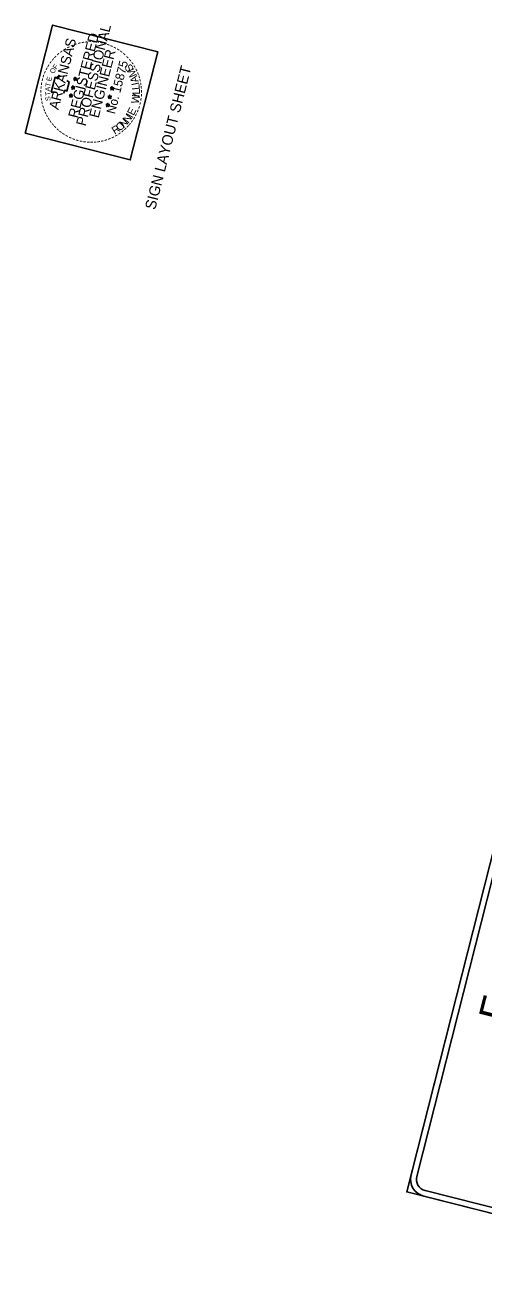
# Model space of a CAD drawing. Extents: x 670257 to 671518, y 737783 to 738188.
# Drawn here: x 670664 to 670687, y 738025.9 to 738088.5 of the extents above; entities that cross this region are included whole.
import ezdxf

# ---------------------------------------------------------------- set-up
doc = ezdxf.new("R2010")
doc.units = 0
for name, color, linetype in [('R_Border Notes', 7, 'Continuous'), ('R_Border PE', 7, 'Continuous'), ('R_Border Prem', 7, 'Continuous'), ('R_SIGN', 7, 'Continuous')]:
    doc.layers.add(name, color=color, linetype=linetype)

msp = doc.modelspace()

# ---------------------------------------------------------------- linework, layer by layer
at = {"layer": 'R_Border PE'}
for p, q in [((670666.448, 738085.809), (670666.513, 738085.811)), ((670666.535, 738085.787), (670666.448, 738085.809)), ((670666.448, 738085.809), (670666.511, 738085.806)), ((670666.448, 738085.809), (670666.507, 738085.799)), ((670666.448, 738085.809), (670666.507, 738085.789)), ((670666.448, 738085.809), (670666.506, 738085.784)), ((670666.448, 738085.809), (670666.502, 738085.78)), ((670666.487, 738085.709), (670666.535, 738085.787)), ((670666.487, 738085.709), (670666.51, 738085.77)), ((670666.487, 738085.709), (670666.514, 738085.767)), ((670666.487, 738085.709), (670666.517, 738085.766)), ((670666.487, 738085.709), (670666.526, 738085.761)), ((670666.487, 738085.709), (670666.531, 738085.76)), ((670666.487, 738085.709), (670666.536, 738085.759)), ((670666.53, 738085.879), (670666.516, 738085.802)), ((670666.53, 738085.879), (670666.524, 738085.805)), ((670666.53, 738085.879), (670666.529, 738085.804)), ((670666.53, 738085.879), (670666.535, 738085.787)), ((670666.53, 738085.879), (670666.538, 738085.82)), ((670666.53, 738085.879), (670666.541, 738085.822)), ((670666.53, 738085.879), (670666.545, 738085.826)), ((670666.594, 738085.716), (670666.534, 738085.762)), ((670666.621, 738085.82), (670666.535, 738085.787)), ((670666.594, 738085.716), (670666.535, 738085.787)), ((670666.621, 738085.82), (670666.542, 738085.806)), ((670666.594, 738085.716), (670666.542, 738085.762)), ((670666.621, 738085.82), (670666.544, 738085.811)), ((670666.594, 738085.716), (670666.545, 738085.767)), ((670666.621, 738085.82), (670666.551, 738085.801)), ((670666.621, 738085.82), (670666.554, 738085.782)), ((670666.594, 738085.716), (670666.554, 738085.782)), ((670666.594, 738085.716), (670666.554, 738085.772)), ((670666.621, 738085.82), (670666.559, 738085.791)), ((670666.621, 738085.82), (670666.562, 738085.78)), ((670666.594, 738085.716), (670666.562, 738085.783)), ((670666.334, 738085.382), (670666.401, 738085.383)), ((670666.424, 738085.359), (670666.334, 738085.382)), ((670666.334, 738085.382), (670666.398, 738085.378)), ((670666.334, 738085.382), (670666.396, 738085.371)), ((670666.334, 738085.382), (670666.393, 738085.361)), ((670666.334, 738085.382), (670666.395, 738085.356)), ((670666.334, 738085.382), (670666.392, 738085.354)), ((670666.376, 738085.281), (670666.424, 738085.359)), ((670666.376, 738085.281), (670666.396, 738085.343)), ((670666.376, 738085.281), (670666.401, 738085.341)), ((670666.376, 738085.281), (670666.406, 738085.338)), ((670666.376, 738085.281), (670666.415, 738085.333)), ((670666.376, 738085.281), (670666.419, 738085.332)), ((670666.376, 738085.281), (670666.424, 738085.33)), ((670666.419, 738085.451), (670666.404, 738085.374)), ((670666.419, 738085.451), (670666.413, 738085.377)), ((670666.419, 738085.451), (670666.418, 738085.376)), ((670666.419, 738085.451), (670666.424, 738085.359)), ((670666.419, 738085.451), (670666.427, 738085.392)), ((670666.419, 738085.451), (670666.431, 738085.396)), ((670666.419, 738085.451), (670666.434, 738085.398)), ((670666.484, 738085.29), (670666.423, 738085.333)), ((670666.51, 738085.394), (670666.424, 738085.359)), ((670666.484, 738085.29), (670666.424, 738085.359)), ((670666.51, 738085.394), (670666.43, 738085.383)), ((670666.484, 738085.29), (670666.43, 738085.334)), ((670666.51, 738085.394), (670666.431, 738085.378)), ((670666.484, 738085.29), (670666.434, 738085.338)), ((670666.51, 738085.394), (670666.44, 738085.373)), ((670666.51, 738085.394), (670666.443, 738085.354)), ((670666.484, 738085.29), (670666.443, 738085.354)), ((670666.484, 738085.29), (670666.443, 738085.344)), ((670666.51, 738085.394), (670666.448, 738085.363)), ((670666.51, 738085.394), (670666.45, 738085.352)), ((670666.484, 738085.29), (670666.451, 738085.355)), ((670668.369, 738085.322), (670668.282, 738085.344)), ((670668.282, 738085.344), (670668.346, 738085.343)), ((670668.282, 738085.344), (670668.346, 738085.341)), ((670668.282, 738085.344), (670668.344, 738085.334)), ((670668.282, 738085.344), (670668.342, 738085.324)), ((670668.282, 738085.344), (670668.34, 738085.319)), ((670668.282, 738085.344), (670668.339, 738085.314)), ((670668.321, 738085.244), (670668.369, 738085.322)), ((670668.321, 738085.244), (670668.344, 738085.303)), ((670668.321, 738085.244), (670668.349, 738085.301)), ((670668.321, 738085.244), (670668.353, 738085.298)), ((670668.321, 738085.244), (670668.36, 738085.296)), ((670668.321, 738085.244), (670668.367, 738085.292)), ((670668.321, 738085.244), (670668.372, 738085.29)), ((670668.364, 738085.411), (670668.35, 738085.337)), ((670668.364, 738085.411), (670668.359, 738085.34)), ((670668.364, 738085.411), (670668.363, 738085.339)), ((670668.364, 738085.411), (670668.369, 738085.322)), ((670668.364, 738085.411), (670668.372, 738085.352)), ((670668.364, 738085.411), (670668.378, 738085.356)), ((670668.364, 738085.411), (670668.381, 738085.358)), ((670668.429, 738085.25), (670668.368, 738085.294)), ((670668.455, 738085.354), (670668.369, 738085.322)), ((670668.429, 738085.25), (670668.369, 738085.322)), ((670668.455, 738085.354), (670668.376, 738085.338)), ((670668.455, 738085.354), (670668.377, 738085.343)), ((670668.429, 738085.25), (670668.378, 738085.294)), ((670668.429, 738085.25), (670668.382, 738085.301)), ((670668.455, 738085.354), (670668.388, 738085.333)), ((670668.429, 738085.25), (670668.389, 738085.307)), ((670668.455, 738085.354), (670668.391, 738085.314)), ((670668.429, 738085.25), (670668.391, 738085.314)), ((670668.455, 738085.354), (670668.393, 738085.324)), ((670668.429, 738085.25), (670668.396, 738085.315)), ((670668.455, 738085.354), (670668.398, 738085.312)), ((670666.232, 738084.977), (670666.299, 738084.978)), ((670666.321, 738084.954), (670666.232, 738084.977)), ((670666.232, 738084.977), (670666.295, 738084.974)), ((670666.232, 738084.977), (670666.294, 738084.969)), ((670666.232, 738084.977), (670666.291, 738084.959)), ((670666.232, 738084.977), (670666.292, 738084.951)), ((670666.232, 738084.977), (670666.289, 738084.95)), ((670666.273, 738084.876), (670666.321, 738084.954)), ((670666.273, 738084.876), (670666.294, 738084.938)), ((670666.273, 738084.876), (670666.299, 738084.937)), ((670666.273, 738084.876), (670666.303, 738084.933)), ((670666.273, 738084.876), (670666.313, 738084.931)), ((670666.273, 738084.876), (670666.317, 738084.927)), ((670666.273, 738084.876), (670666.322, 738084.926)), ((670666.316, 738085.046), (670666.302, 738084.969)), ((670666.316, 738085.046), (670666.31, 738084.972)), ((670666.316, 738085.046), (670666.315, 738084.971)), ((670666.316, 738085.046), (670666.321, 738084.954)), ((670666.316, 738085.046), (670666.324, 738084.987)), ((670666.316, 738085.046), (670666.328, 738084.991)), ((670666.316, 738085.046), (670666.331, 738084.993)), ((670666.381, 738084.885), (670666.32, 738084.929)), ((670666.407, 738084.989), (670666.321, 738084.954)), ((670666.381, 738084.885), (670666.321, 738084.954)), ((670666.407, 738084.989), (670666.327, 738084.978)), ((670666.381, 738084.885), (670666.328, 738084.929)), ((670666.407, 738084.989), (670666.329, 738084.973)), ((670666.381, 738084.885), (670666.331, 738084.934)), ((670666.407, 738084.989), (670666.338, 738084.968)), ((670666.407, 738084.989), (670666.341, 738084.949)), ((670666.381, 738084.885), (670666.341, 738084.949)), ((670666.381, 738084.885), (670666.341, 738084.939)), ((670666.407, 738084.989), (670666.345, 738084.958)), ((670666.407, 738084.989), (670666.348, 738084.947)), ((670666.381, 738084.885), (670666.348, 738084.95)), ((670668.068, 738084.511), (670668.133, 738084.513)), ((670668.156, 738084.489), (670668.068, 738084.511)), ((670668.068, 738084.511), (670668.132, 738084.508)), ((670668.068, 738084.511), (670668.13, 738084.501)), ((670668.068, 738084.511), (670668.128, 738084.491)), ((670668.068, 738084.511), (670668.126, 738084.486)), ((670668.068, 738084.511), (670668.123, 738084.482)), ((670668.107, 738084.411), (670668.156, 738084.489)), ((670668.107, 738084.411), (670668.131, 738084.472)), ((670668.107, 738084.411), (670668.135, 738084.468)), ((670668.107, 738084.411), (670668.137, 738084.468)), ((670668.107, 738084.411), (670668.146, 738084.463)), ((670668.107, 738084.411), (670668.151, 738084.462)), ((670668.107, 738084.411), (670668.156, 738084.461)), ((670668.15, 738084.581), (670668.136, 738084.504)), ((670668.15, 738084.581), (670668.145, 738084.507)), ((670668.15, 738084.581), (670668.156, 738084.489)), ((670668.15, 738084.581), (670668.15, 738084.506)), ((670668.15, 738084.581), (670668.158, 738084.519)), ((670668.15, 738084.581), (670668.162, 738084.524)), ((670668.15, 738084.581), (670668.168, 738084.527)), ((670668.215, 738084.417), (670668.154, 738084.464)), ((670668.241, 738084.521), (670668.156, 738084.489)), ((670668.215, 738084.417), (670668.156, 738084.489)), ((670668.241, 738084.521), (670668.162, 738084.505)), ((670668.241, 738084.521), (670668.164, 738084.513)), ((670668.215, 738084.417), (670668.165, 738084.464)), ((670668.215, 738084.417), (670668.168, 738084.468)), ((670668.258, 738084.894), (670668.171, 738084.916)), ((670668.171, 738084.916), (670668.235, 738084.915)), ((670668.171, 738084.916), (670668.235, 738084.913)), ((670668.171, 738084.916), (670668.233, 738084.905)), ((670668.171, 738084.916), (670668.23, 738084.896)), ((670668.171, 738084.916), (670668.229, 738084.891)), ((670668.171, 738084.916), (670668.225, 738084.887)), ((670668.241, 738084.521), (670668.172, 738084.503)), ((670668.215, 738084.417), (670668.175, 738084.484)), ((670668.215, 738084.417), (670668.175, 738084.474)), ((670668.241, 738084.521), (670668.177, 738084.483)), ((670668.241, 738084.521), (670668.179, 738084.491)), ((670668.241, 738084.521), (670668.182, 738084.48)), ((670668.215, 738084.417), (670668.182, 738084.482)), ((670668.21, 738084.816), (670668.258, 738084.894)), ((670668.21, 738084.816), (670668.233, 738084.874)), ((670668.21, 738084.816), (670668.238, 738084.873)), ((670668.21, 738084.816), (670668.24, 738084.873)), ((670668.21, 738084.816), (670668.249, 738084.868)), ((670668.21, 738084.816), (670668.254, 738084.866)), ((670668.21, 738084.816), (670668.259, 738084.865)), ((670668.252, 738084.983), (670668.239, 738084.909)), ((670668.252, 738084.983), (670668.247, 738084.912)), ((670668.252, 738084.983), (670668.258, 738084.894)), ((670668.252, 738084.983), (670668.252, 738084.911)), ((670668.252, 738084.983), (670668.261, 738084.924)), ((670668.252, 738084.983), (670668.264, 738084.928)), ((670668.252, 738084.983), (670668.27, 738084.932)), ((670668.317, 738084.822), (670668.257, 738084.868)), ((670668.344, 738084.926), (670668.258, 738084.894)), ((670668.317, 738084.822), (670668.258, 738084.894)), ((670668.344, 738084.926), (670668.265, 738084.91)), ((670668.344, 738084.926), (670668.267, 738084.917)), ((670668.317, 738084.822), (670668.267, 738084.868)), ((670668.317, 738084.822), (670668.271, 738084.872)), ((670668.344, 738084.926), (670668.275, 738084.908)), ((670668.317, 738084.822), (670668.278, 738084.889)), ((670668.317, 738084.822), (670668.278, 738084.878)), ((670668.344, 738084.926), (670668.28, 738084.888)), ((670668.344, 738084.926), (670668.282, 738084.895)), ((670668.344, 738084.926), (670668.284, 738084.885)), ((670668.317, 738084.822), (670668.285, 738084.887))]:
    msp.add_line(p, q, dxfattribs=at)
for points in [[(670665.775, 738085.921), (670665.715, 738085.972), (670665.678, 738085.804), (670665.527, 738085.88), (670665.336, 738085.127)], [(670665.952, 738085.097), (670665.974, 738085.091), (670666.013, 738085.226), (670666.124, 738085.185), (670666.239, 738085.638), (670666.123, 738085.719)], [(670666.448, 738085.809), (670666.621, 738085.82), (670666.487, 738085.709), (670666.53, 738085.879), (670666.594, 738085.716), (670666.448, 738085.809)], [(670665.336, 738085.127), (670665.553, 738085.139)], [(670666.334, 738085.382), (670666.51, 738085.394), (670666.376, 738085.281), (670666.419, 738085.451), (670666.484, 738085.29), (670666.334, 738085.382)], [(670668.282, 738085.344), (670668.455, 738085.354), (670668.321, 738085.244), (670668.364, 738085.411), (670668.429, 738085.25), (670668.282, 738085.344)], [(670666.232, 738084.977), (670666.407, 738084.989), (670666.273, 738084.876), (670666.316, 738085.046), (670666.381, 738084.885), (670666.232, 738084.977)], [(670668.068, 738084.511), (670668.241, 738084.521), (670668.107, 738084.411), (670668.15, 738084.581), (670668.215, 738084.417), (670668.068, 738084.511)], [(670668.171, 738084.916), (670668.344, 738084.926), (670668.21, 738084.816), (670668.252, 738084.983), (670668.317, 738084.822), (670668.171, 738084.916)]]:
    msp.add_lwpolyline(points, dxfattribs=at)
for centre, radius in [((670666.536, 738085.787), 0.0431), ((670666.536, 738085.787), 0.039), ((670666.536, 738085.787), 0.0361), ((670666.536, 738085.787), 0.0332), ((670666.536, 738085.787), 0.0289), ((670666.536, 738085.787), 0.0269), ((670666.536, 738085.787), 0.0248), ((670666.536, 738085.787), 0.0213), ((670666.536, 738085.787), 0.0187), ((670666.536, 738085.787), 0.0155), ((670666.536, 738085.787), 0.0124), ((670666.536, 738085.787), 0.00924), ((670666.536, 738085.787), 0.00741), ((670666.536, 738085.787), 0.0036), ((670666.424, 738085.359), 0.0431), ((670666.424, 738085.359), 0.039), ((670666.424, 738085.359), 0.0361), ((670666.424, 738085.359), 0.0332), ((670666.424, 738085.359), 0.0289), ((670666.424, 738085.359), 0.0269), ((670666.424, 738085.359), 0.0248), ((670666.424, 738085.359), 0.0213), ((670666.424, 738085.359), 0.0187), ((670666.424, 738085.359), 0.0155), ((670666.424, 738085.359), 0.0124), ((670666.424, 738085.359), 0.00924), ((670666.424, 738085.359), 0.00741), ((670666.424, 738085.359), 0.0036), ((670668.37, 738085.32), 0.0431), ((670668.37, 738085.32), 0.039), ((670668.37, 738085.32), 0.0361), ((670668.37, 738085.32), 0.0332), ((670668.37, 738085.32), 0.0289), ((670668.37, 738085.32), 0.0269), ((670668.37, 738085.32), 0.0248), ((670668.37, 738085.32), 0.0213), ((670668.37, 738085.32), 0.0187), ((670668.37, 738085.32), 0.0155), ((670668.37, 738085.32), 0.0124), ((670668.37, 738085.32), 0.00924), ((670668.37, 738085.32), 0.00741), ((670668.37, 738085.32), 0.0036), ((670666.322, 738084.955), 0.0431), ((670666.322, 738084.955), 0.039), ((670666.322, 738084.955), 0.0361), ((670666.322, 738084.955), 0.0332), ((670666.322, 738084.955), 0.0289), ((670666.322, 738084.955), 0.0269), ((670666.322, 738084.955), 0.0248), ((670666.322, 738084.955), 0.0213), ((670666.322, 738084.955), 0.0187), ((670666.322, 738084.955), 0.0155), ((670666.322, 738084.955), 0.0124), ((670666.322, 738084.955), 0.00924), ((670666.322, 738084.955), 0.00741), ((670666.322, 738084.955), 0.0036), ((670668.156, 738084.488), 0.0431), ((670668.156, 738084.488), 0.039), ((670668.156, 738084.488), 0.0361), ((670668.156, 738084.488), 0.0332), ((670668.156, 738084.488), 0.0289), ((670668.156, 738084.488), 0.0269), ((670668.156, 738084.488), 0.0248), ((670668.156, 738084.488), 0.0213), ((670668.156, 738084.488), 0.0187), ((670668.156, 738084.488), 0.0155), ((670668.156, 738084.488), 0.0124), ((670668.156, 738084.488), 0.00924), ((670668.156, 738084.488), 0.00741), ((670668.156, 738084.488), 0.0036), ((670668.259, 738084.893), 0.0431), ((670668.259, 738084.893), 0.039), ((670668.259, 738084.893), 0.0361), ((670668.259, 738084.893), 0.0332), ((670668.259, 738084.893), 0.0289), ((670668.259, 738084.893), 0.0269), ((670668.259, 738084.893), 0.0248), ((670668.259, 738084.893), 0.0213), ((670668.259, 738084.893), 0.0187), ((670668.259, 738084.893), 0.0155), ((670668.259, 738084.893), 0.0124), ((670668.259, 738084.893), 0.00924), ((670668.259, 738084.893), 0.00741), ((670668.259, 738084.893), 0.0036)]:
    msp.add_circle(centre, radius, dxfattribs=at)
at = {"layer": 'R_Border Prem'}
msp.add_lwpolyline([(670664.03, 738083.077), (670665.402, 738088.486), (670670.66, 738087.152), (670669.288, 738081.744)], close=True, dxfattribs=at)
at = {"layer": 'R_SIGN'}
for points in [[(670700.058, 738025.853), (670707.802, 738056.386), (670690.839, 738060.689), (670683.095, 738030.155), (670700.058, 738025.853), (670700.058, 738025.853)], [(670683.31, 738031.003), (670690.624, 738059.84)], [(670690.906, 738059.769), (670683.593, 738030.932)], [(670699.21, 738026.068), (670683.943, 738029.94)], [(670684.015, 738030.223), (670699.281, 738026.351)]]:
    msp.add_lwpolyline(points, dxfattribs=at)
for radius in [0.875, 0.583]:
    msp.add_arc((670684.158, 738030.788), radius, 165.76876, 255.7684, dxfattribs=at)

# ---------------------------------------------------------------- texts
at = {"layer": 'R_Border Notes'}
msp.add_text('SIGN LAYOUT SHEET', height=0.53359, rotation=75.76855, dxfattribs=at).set_placement((670670.528, 738079.22))
at = {"layer": 'R_Border PE'}
for s, height, rotation, p in [('PROFESSIONAL', 0.5, 75.76855, (670667.051, 738083.407)), ('ARKANSAS', 0.5, 75.76855, (670665.697, 738084.223)), ('REGISTERED', 0.5, 75.76855, (670666.661, 738083.803)), ('-', 0.35, 19.44384, (670666.524, 738087.371)), ('-', 0.4, 15.4369, (670666.692, 738087.411)), ('-', 0.4, 10.43135, (670666.859, 738087.451)), ('-', 0.4, 6.34138, (670667.013, 738087.479)), ('-', 0.4, 0.89181, (670667.168, 738087.499)), ('-', 0.4, 356.31789, (670667.362, 738087.502)), ('-', 0.4, 352.36471, (670667.556, 738087.496)), ('-', 0.4, 350.09866, (670667.737, 738087.466)), ('-', 0.4, 345.70922, (670667.892, 738087.434)), ('-', 0.4, 45.40945, (670665.586, 738086.724)), ('-', 0.4, 41.63121, (670665.713, 738086.857)), ('-', 0.4, 36.29826, (670665.855, 738086.979)), ('-', 0.4, 31.34714, (670666.01, 738087.094)), ('-', 0.4, 25.64828, (670666.178, 738087.198)), ('-', 0.4, 22.42073, (670666.356, 738087.287)), ('ENGINEER', 0.5, 75.76855, (670667.702, 738083.807)), ('-', 0.4, 339.28575, (670668.05, 738087.389)), ('-', 0.4, 336.76384, (670668.206, 738087.331)), ('-', 0.4, 331.53115, (670668.364, 738087.263)), ('-', 0.4, 328.63664, (670668.527, 738087.175)), ('-', 0.4, 323.65722, (670668.676, 738087.081)), ('-', 0.4, 320.38827, (670668.812, 738086.976)), ('-', 0.4, 314.8398, (670668.97, 738086.836)), ('-', 0.4, 62.97344, (670665.202, 738086.156)), ('-', 0.4, 58.10475, (670665.28, 738086.299)), ('-', 0.4, 53.62364, (670665.379, 738086.465)), ('O', 0.25, 66.22005, (670665.48, 738086.032)), ('-', 0.4, 49.88964, (670665.483, 738086.601)), ('F', 0.25, 55.83921, (670665.594, 738086.248)), ('No. 15875', 0.44, 75.76855, (670668.515, 738084.013)), ('S', 0.385, 121.46196, (670669.484, 738086.288)), ('M', 0.385, 113.32556, (670669.625, 738085.972)), ('-', 0.4, 309.61379, (670669.103, 738086.699)), ('-', 0.4, 307.02232, (670669.215, 738086.56)), ('-', 0.4, 301.53388, (670669.321, 738086.409)), ('-', 0.4, 296.85364, (670669.412, 738086.252)), ('-', 0.4, 75.95478, (670665.024, 738085.637)), ('-', 0.4, 73.51159, (670665.071, 738085.813)), ('-', 0.4, 67.93028, (670665.131, 738085.988)), ('E', 0.25, 76.60089, (670665.33, 738085.654)), ('A', 0.385, 105.76014, (670669.714, 738085.663)), ('-', 0.4, 291.50488, (670669.493, 738086.089)), ('-', 0.4, 288.01764, (670669.554, 738085.935)), ('-', 0.4, 283.12539, (670669.605, 738085.78)), ('-', 0.4, 89.3987, (670664.973, 738085.087)), ('-', 0.4, 85.9879, (670664.976, 738085.262)), ('-', 0.4, 81.66537, (670664.994, 738085.446)), ('T', 0.25, 92.17215, (670665.288, 738084.948)), ('A', 0.25, 86.98173, (670665.278, 738085.165)), ('T', 0.25, 81.79131, (670665.289, 738085.381)), ('W', 0.385, 78.78155, (670669.693, 738084.526)), ('I', 0.385, 102.33428, (670669.741, 738085.52)), ('L', 0.385, 96.33904, (670669.768, 738085.267)), ('L', 0.385, 90.3438, (670669.768, 738085.012)), ('-', 0.4, 280.02017, (670669.644, 738085.607)), ('-', 0.4, 276.48697, (670669.671, 738085.441)), ('-', 0.4, 271.24284, (670669.688, 738085.264)), ('-', 0.4, 94.94463, (670664.985, 738084.891)), ('-', 0.4, 100.07576, (670665.011, 738084.722)), ('-', 0.4, 104.56037, (670665.05, 738084.549)), ('-', 0.4, 109.83212, (670665.103, 738084.381)), ('S', 0.25, 97.36257, (670665.312, 738084.707)), ('I', 0.385, 86.91795, (670669.756, 738084.867)), ('-', 0.4, 252.28682, (670669.607, 738084.505)), ('-', 0.4, 257.36031, (670669.647, 738084.686)), ('-', 0.4, 261.58522, (670669.678, 738084.887)), ('-', 0.4, 267.05431, (670669.692, 738085.074)), ('-', 0.4, 112.00029, (670665.162, 738084.217)), ('-', 0.4, 114.71921, (670665.225, 738084.079)), ('-', 0.4, 118.7308, (670665.3, 738083.947)), ('-', 0.4, 124.1916, (670665.388, 738083.808)), ('N', 0.385, 45.16538, (670668.959, 738083.323)), ('N', 0.385, 52.7308, (670669.184, 738083.553)), ('I', 0.385, 60.29623, (670669.377, 738083.81)), ('E', 0.385, 63.72208, (670669.453, 738083.935)), ('-', 0.4, 238.56682, (670669.389, 738083.983)), ('-', 0.4, 243.32407, (670669.472, 738084.147)), ('-', 0.4, 248.88401, (670669.546, 738084.327)), ('-', 0.4, 126.38273, (670665.48, 738083.682)), ('-', 0.4, 130.00102, (670665.593, 738083.548)), ('-', 0.4, 133.83918, (670665.701, 738083.435)), ('-', 0.4, 138.6399, (670665.83, 738083.322)), ('-', 0.4, 143.54282, (670665.962, 738083.222)), ('R', 0.385, 32.17569, (670668.509, 738083.004)), ('O', 0.385, 38.88465, (670668.75, 738083.156)), ('-', 0.4, 220.41489, (670668.865, 738083.35)), ('-', 0.4, 223.85834, (670668.989, 738083.463)), ('-', 0.4, 227.33894, (670669.104, 738083.583)), ('-', 0.4, 230.36875, (670669.195, 738083.694)), ('-', 0.4, 234.32977, (670669.296, 738083.831)), ('-', 0.4, 148.16302, (670666.101, 738083.13)), ('-', 0.4, 151.22951, (670666.264, 738083.04)), ('-', 0.4, 156.96982, (670666.427, 738082.962)), ('-', 0.4, 160.95489, (670666.59, 738082.903)), ('-', 0.4, 164.83079, (670666.758, 738082.852)), ('-', 0.4, 169.96443, (670666.937, 738082.817)), ('-', 0.4, 174.71648, (670667.101, 738082.794)), ('-', 0.4, 177.4835, (670667.289, 738082.78)), ('-', 0.4, 181.2264, (670667.442, 738082.785)), ('-', 0.4, 184.85597, (670667.608, 738082.797)), ('-', 0.4, 189.83287, (670667.769, 738082.823)), ('-', 0.4, 191.4974, (670667.938, 738082.857)), ('-', 0.4, 196.21567, (670668.1, 738082.909)), ('-', 0.4, 201.662, (670668.261, 738082.972)), ('-', 0.4, 206.48667, (670668.425, 738083.049)), ('-', 0.4, 209.99236, (670668.588, 738083.141)), ('-', 0.4, 214.70237, (670668.731, 738083.239))]:
    msp.add_text(s, height=height, rotation=rotation, dxfattribs=at).set_placement(p)
at = {"layer": 'R_SIGN'}
msp.add_text('F', height=1.458, rotation=75.76855, dxfattribs=at).set_placement((670688.084, 738038.556))

doc.saveas('drawing.dxf')
